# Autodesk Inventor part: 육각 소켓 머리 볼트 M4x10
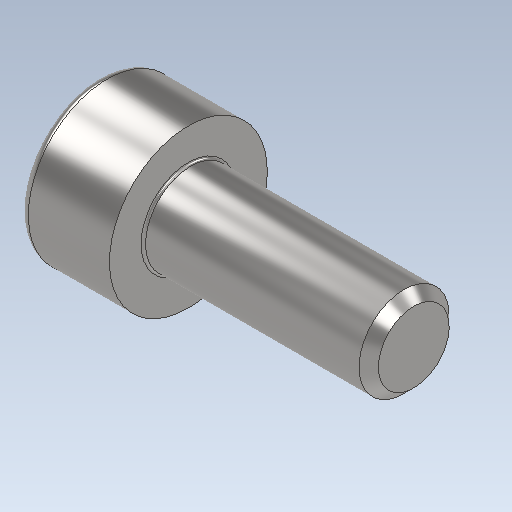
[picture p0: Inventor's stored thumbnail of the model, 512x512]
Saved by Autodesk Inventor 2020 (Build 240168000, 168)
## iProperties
Created: 2024-08
Part Number: 육각 소켓 머리 볼트 M4x10
Material: 강철, 연강
Description: 6각머리 태핑 나사
Document SubType Name: Modeling
Designer: oem
Density: 7.85 g/cm^3
Appearance: 기본값
Author: jhkim
Sending System: Autodesk Inventor 2025
Preprocessor: ST-DEVELOPER v20
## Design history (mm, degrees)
node "육각 소켓 머리 볼트 M4x101"
node "솔리드1"
body "Solid1"
